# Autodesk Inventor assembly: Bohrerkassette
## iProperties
Created: 2007-04
Part Number: Bohrerkassette
Document SubType Name: Assembly
Designer: Benno
Manufacturer: Standard
Standards Organization: Custom
Author: Benno
